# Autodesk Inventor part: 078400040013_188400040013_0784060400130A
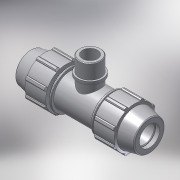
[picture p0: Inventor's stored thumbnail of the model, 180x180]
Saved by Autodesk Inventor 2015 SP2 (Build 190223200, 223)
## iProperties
Created: 2017-02
Part Number: 078400040013_188400040013_0784060400130A
Material: PVC-Piping
Description: PLASSON TEE WITH THREADED MALE OFFTAKE 40-1.1/4"-40
Document SubType Name: Modeling
Designer: KIM
Mass: 92.6774 g
Surface Area: 199.44 cm^2
Volume: 66.1981 cm^3
Density: 1.4 g/cm^3
Appearance: Smooth - White
Author: Кирилл
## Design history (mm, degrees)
derived "07840.ipt"
feature "Solid1::07840.ipt"
feature "Solid2::07840.ipt"
tag "TaggingFeature1"
body "Solid1"
body "Solid2"
other parameters: "d4" = 8.54167, "d5" = 24.6, "d7" = 82, "d11" = 3.41667, "d13" = 120 deg, "d15" = 12 deg, "d16" = 71.34, "d18" = 2, "d19" = 35 deg, "d20" = 17.5 deg, "d21" = 76.26, "d23" = 0, "d25" = 360 deg, "d27" = 1.64, "d33" = 0.8, "d42" = 36.9, "d43" = 2.46, "d46" = 1.2, "d68" = 3.41667, "d72" = 71, "d73" = 41.91, "d74" = 22, "d75" = 48.1965, "d76" = 29.337, "d77" = 26.4, "d80" = 1.2573, "d91" = 61.5, "d93" = 84, "d95" = 36, "d99" = 205, "d101" = 0, "d103" = 0, "d105" = 0, "E_" = 82, "A_" = 71, "l_" = 84, "l_2" = 22, "H_" = 205, "R_" = 41.91
